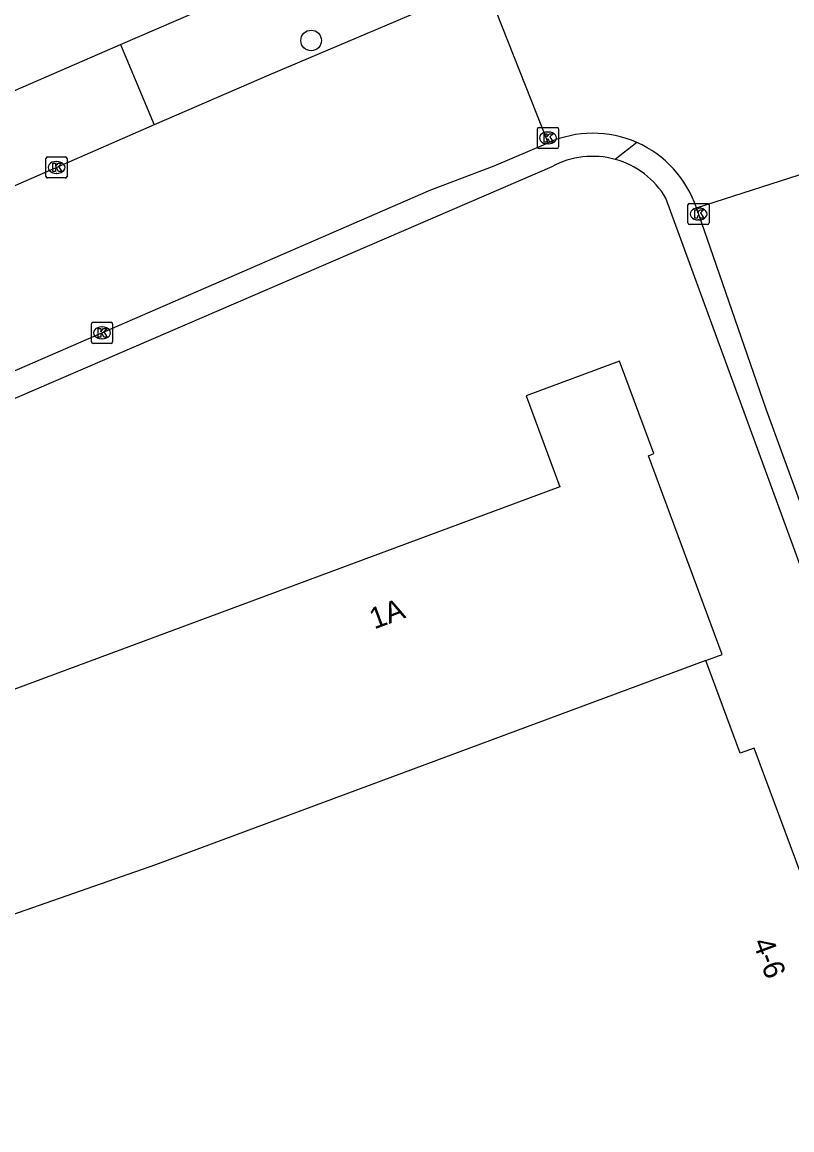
# Model space of a CAD drawing. Extents: x 158087 to 159494, y 382905 to 383981.
# Drawn here: x 158950.2 to 158986.6, y 383089.4 to 383141.9 of the extents above; entities that cross this region are included whole.
import ezdxf

# ---------------------------------------------------------------- set-up
doc = ezdxf.new("R2010")
doc.units = 0
for name, color, linetype in [('IMGEO_Boom', 7, 'Continuous'), ('IMGEO_Kolk', 7, 'Continuous'), ('IMGEO_Pand', 7, 'Continuous'), ('IMGEO_Pand_nummerreeks', 7, 'Continuous'), ('IMGEO_Rijbaan_lokaal_open', 7, 'Continuous'), ('IMGEO_Voetpad_open', 7, 'Continuous')]:
    doc.layers.add(name, color=color, linetype=linetype)

msp = doc.modelspace()

# ---------------------------------------------------------------- linework, layer by layer
at = {"layer": 'IMGEO_Boom'}
msp.add_circle((158963.834, 383141.016), 0.489, dxfattribs=at)
at = {"layer": 'IMGEO_Kolk'}
for p, q in [((158974.549, 383135.972), (158974.549, 383136.824)), ((158974.624, 383136.898), (158975.476, 383136.898)), ((158975.55, 383136.824), (158975.55, 383135.972)), ((158975.037, 383136.678), (158975.062, 383136.678)), ((158975.476, 383135.898), (158974.624, 383135.898)), ((158975.06, 383136.118), (158975.035, 383136.118)), ((158951.277, 383134.573), (158951.277, 383135.425)), ((158951.352, 383135.499), (158952.204, 383135.499)), ((158951.765, 383135.279), (158951.79, 383135.279)), ((158952.278, 383135.425), (158952.278, 383134.573)), ((158951.788, 383134.719), (158951.763, 383134.719)), ((158952.204, 383134.499), (158951.352, 383134.499)), ((158981.678, 383132.367), (158981.678, 383133.219)), ((158981.753, 383133.293), (158982.605, 383133.293)), ((158982.679, 383133.219), (158982.679, 383132.367)), ((158982.166, 383133.073), (158982.191, 383133.073)), ((158982.605, 383132.293), (158981.753, 383132.293)), ((158982.189, 383132.513), (158982.164, 383132.513)), ((158953.431, 383126.735), (158953.431, 383127.587)), ((158953.506, 383127.661), (158954.358, 383127.661)), ((158953.919, 383127.441), (158953.944, 383127.441)), ((158954.432, 383127.587), (158954.432, 383126.735)), ((158953.942, 383126.881), (158953.917, 383126.881)), ((158954.358, 383126.661), (158953.506, 383126.661))]:
    msp.add_line(p, q, dxfattribs=at)
for points in [[(158974.549, 383135.972), (158974.549, 383136.824)], [(158974.624, 383136.898), (158975.476, 383136.898)], [(158975.55, 383136.824), (158975.55, 383135.972)], [(158974.87, 383136.598), (158974.993, 383136.598), (158974.993, 383136.447), (158975.123, 383136.598), (158975.287, 383136.598), (158975.141, 383136.447), (158975.294, 383136.198), (158975.142, 383136.198), (158975.057, 383136.362), (158974.993, 383136.295), (158974.993, 383136.198), (158974.87, 383136.198), (158974.87, 383136.598)], [(158975.476, 383135.898), (158974.624, 383135.898)], [(158951.277, 383134.573), (158951.277, 383135.425)], [(158951.352, 383135.499), (158952.204, 383135.499)], [(158952.278, 383135.425), (158952.278, 383134.573)], [(158951.598, 383135.199), (158951.721, 383135.199), (158951.721, 383135.048), (158951.851, 383135.199), (158952.015, 383135.199), (158951.869, 383135.048), (158952.022, 383134.799), (158951.87, 383134.799), (158951.785, 383134.963), (158951.721, 383134.896), (158951.721, 383134.799), (158951.598, 383134.799), (158951.598, 383135.199)], [(158952.204, 383134.499), (158951.352, 383134.499)], [(158981.678, 383132.367), (158981.678, 383133.219)], [(158981.753, 383133.293), (158982.605, 383133.293)], [(158982.679, 383133.219), (158982.679, 383132.367)], [(158981.999, 383132.993), (158982.122, 383132.993), (158982.122, 383132.842), (158982.252, 383132.993), (158982.416, 383132.993), (158982.27, 383132.842), (158982.423, 383132.593), (158982.271, 383132.593), (158982.186, 383132.757), (158982.122, 383132.69), (158982.122, 383132.593), (158981.999, 383132.593), (158981.999, 383132.993)], [(158982.605, 383132.293), (158981.753, 383132.293)], [(158953.431, 383126.735), (158953.431, 383127.587)], [(158953.506, 383127.661), (158954.358, 383127.661)], [(158953.752, 383127.361), (158953.875, 383127.361), (158953.875, 383127.21), (158954.005, 383127.361), (158954.169, 383127.361), (158954.023, 383127.21), (158954.176, 383126.961), (158954.024, 383126.961), (158953.939, 383127.125), (158953.875, 383127.058), (158953.875, 383126.961), (158953.752, 383126.961), (158953.752, 383127.361)], [(158954.432, 383127.587), (158954.432, 383126.735)], [(158954.358, 383126.661), (158953.506, 383126.661)]]:
    msp.add_lwpolyline(points, dxfattribs=at)
for centre, start, end in [((158974.626, 383136.822), 91.552, 178.448), ((158974.626, 383136.822), 91.552, 178.448), ((158975.474, 383136.822), 1.552, 88.448), ((158975.474, 383136.822), 1.552, 88.448), ((158974.626, 383135.974), 181.552, 268.448), ((158974.626, 383135.974), 181.552, 268.448), ((158975.474, 383135.974), 271.552, 358.448), ((158975.474, 383135.974), 271.552, 358.448), ((158951.354, 383135.423), 91.552, 178.448), ((158951.354, 383135.423), 91.552, 178.448), ((158952.202, 383135.423), 1.552, 88.448), ((158952.202, 383135.423), 1.552, 88.448), ((158951.354, 383134.575), 181.552, 268.448), ((158951.354, 383134.575), 181.552, 268.448), ((158952.202, 383134.575), 271.552, 358.448), ((158952.202, 383134.575), 271.552, 358.448), ((158981.755, 383133.217), 91.552, 178.448), ((158981.755, 383133.217), 91.552, 178.448), ((158982.603, 383133.217), 1.552, 88.448), ((158982.603, 383133.217), 1.552, 88.448), ((158981.755, 383132.369), 181.552, 268.448), ((158981.755, 383132.369), 181.552, 268.448), ((158982.603, 383132.369), 271.552, 358.448), ((158982.603, 383132.369), 271.552, 358.448), ((158953.508, 383127.585), 91.552, 178.448), ((158953.508, 383127.585), 91.552, 178.448), ((158954.356, 383127.585), 1.552, 88.448), ((158954.356, 383127.585), 1.552, 88.448), ((158953.508, 383126.737), 181.552, 268.448), ((158953.508, 383126.737), 181.552, 268.448), ((158954.356, 383126.737), 271.552, 358.448), ((158954.356, 383126.737), 271.552, 358.448)]:
    msp.add_arc(centre, 0.0765, start, end, dxfattribs=at)
for centre, major_axis, ratio, start_param, end_param in [((158975.036, 383136.398), (-0.387, 0.002), 0.722429, 4.712389, 7.853982), ((158975.061, 383136.398), (-0.39, 0.002), 0.717154, 1.570796, 4.712389), ((158951.764, 383134.999), (-0.387, 0.002), 0.722429, 4.712389, 7.853982), ((158951.789, 383134.999), (-0.39, 0.002), 0.717154, 1.570796, 4.712389), ((158982.165, 383132.793), (-0.387, 0.002), 0.722429, 4.712389, 7.853982), ((158982.19, 383132.793), (-0.39, 0.002), 0.717154, 1.570796, 4.712389), ((158953.918, 383127.161), (-0.387, 0.002), 0.722429, 4.712389, 7.853982), ((158953.943, 383127.161), (-0.39, 0.002), 0.717154, 1.570796, 4.712389)]:
    msp.add_ellipse(centre, major_axis=major_axis, ratio=ratio, start_param=start_param, end_param=end_param, dxfattribs=at)
at = {"layer": 'IMGEO_Pand'}
for points in [[(158982.521, 383111.63), (158983.304, 383111.921), (158979.805, 383121.339), (158980.059, 383121.434), (158978.429, 383125.821), (158974.015, 383124.181), (158975.616, 383119.869), (158941.834, 383107.313)], [(158982.521, 383111.63), (158956.46, 383101.94), (158945.753, 383098.203)], [(158993.633, 383083.633), (158993.553, 383083.847), (158992.822, 383083.576), (158991.178, 383088), (158991.945, 383088.285), (158984.812, 383107.476), (158984.156, 383107.233), (158982.521, 383111.63)]]:
    msp.add_lwpolyline(points, dxfattribs=at)
at = {"layer": 'IMGEO_Rijbaan_lokaal_open'}
for points in [[(158972.076, 383143.74), (158961.828, 383139.38), (158956.401, 383137.015)], [(158975.064, 383136.167), (158972.076, 383143.74)], [(158956.401, 383137.015), (158949.067, 383133.818), (158942.083, 383130.86)], [(158942.408, 383122.151), (158948.459, 383124.786), (158969.499, 383133.933), (158972.498, 383135.073), (158975.064, 383136.167)], [(158982.077, 383133.078), (158991.322, 383136.048), (158991.444, 383136.082)], [(158988.889, 383113.943), (158985.382, 383123.536), (158982.594, 383131.636), (158982.077, 383133.078)]]:
    msp.add_lwpolyline(points, dxfattribs=at)
for centre, radius, start, end in [((158977.177, 383131.464), 5.156, 66.2115, 114.1984), ((158977.178, 383131.46), 5.159, 18.2757, 66.2349)]:
    msp.add_arc(centre, radius, start, end, dxfattribs=at)
at = {"layer": 'IMGEO_Voetpad_open'}
for points in [[(158954.808, 383140.824), (158965.125, 383145.296), (158970.2, 383147.496), (158979.866, 383151.686)], [(158947.27, 383137.556), (158954.808, 383140.824)], [(158954.808, 383140.824), (158956.401, 383137.015)], [(158979.257, 383136.182), (158978.233, 383135.381)], [(158975.23, 383135.031), (158942.876, 383121.069)], [(158987.936, 383113.554), (158980.634, 383133.543)]]:
    msp.add_lwpolyline(points, dxfattribs=at)
for centre, radius, start, end in [((158977.164, 383131.492), 4.033, 74.6337, 118.6619), ((158977.162, 383131.495), 4.03, 30.534, 74.5969)]:
    msp.add_arc(centre, radius, start, end, dxfattribs=at)

# ---------------------------------------------------------------- texts
at = {"layer": 'IMGEO_Pand_nummerreeks'}
for s, rotation, p in [('1A', 20.3916, (158966.826, 383113.104)), ('4-6', 290.3914, (158984.732, 383098.278))]:
    msp.add_text(s, height=1, rotation=rotation, dxfattribs=at).set_placement(p)

doc.saveas('drawing.dxf')
